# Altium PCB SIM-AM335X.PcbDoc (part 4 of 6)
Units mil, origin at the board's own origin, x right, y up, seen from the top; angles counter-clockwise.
Board outline 4041.51 x 2715.24 mil, 2 copper layers (Top Layer, Bottom Layer); 172 components, 190 nets, 855 pads, 317 vias.
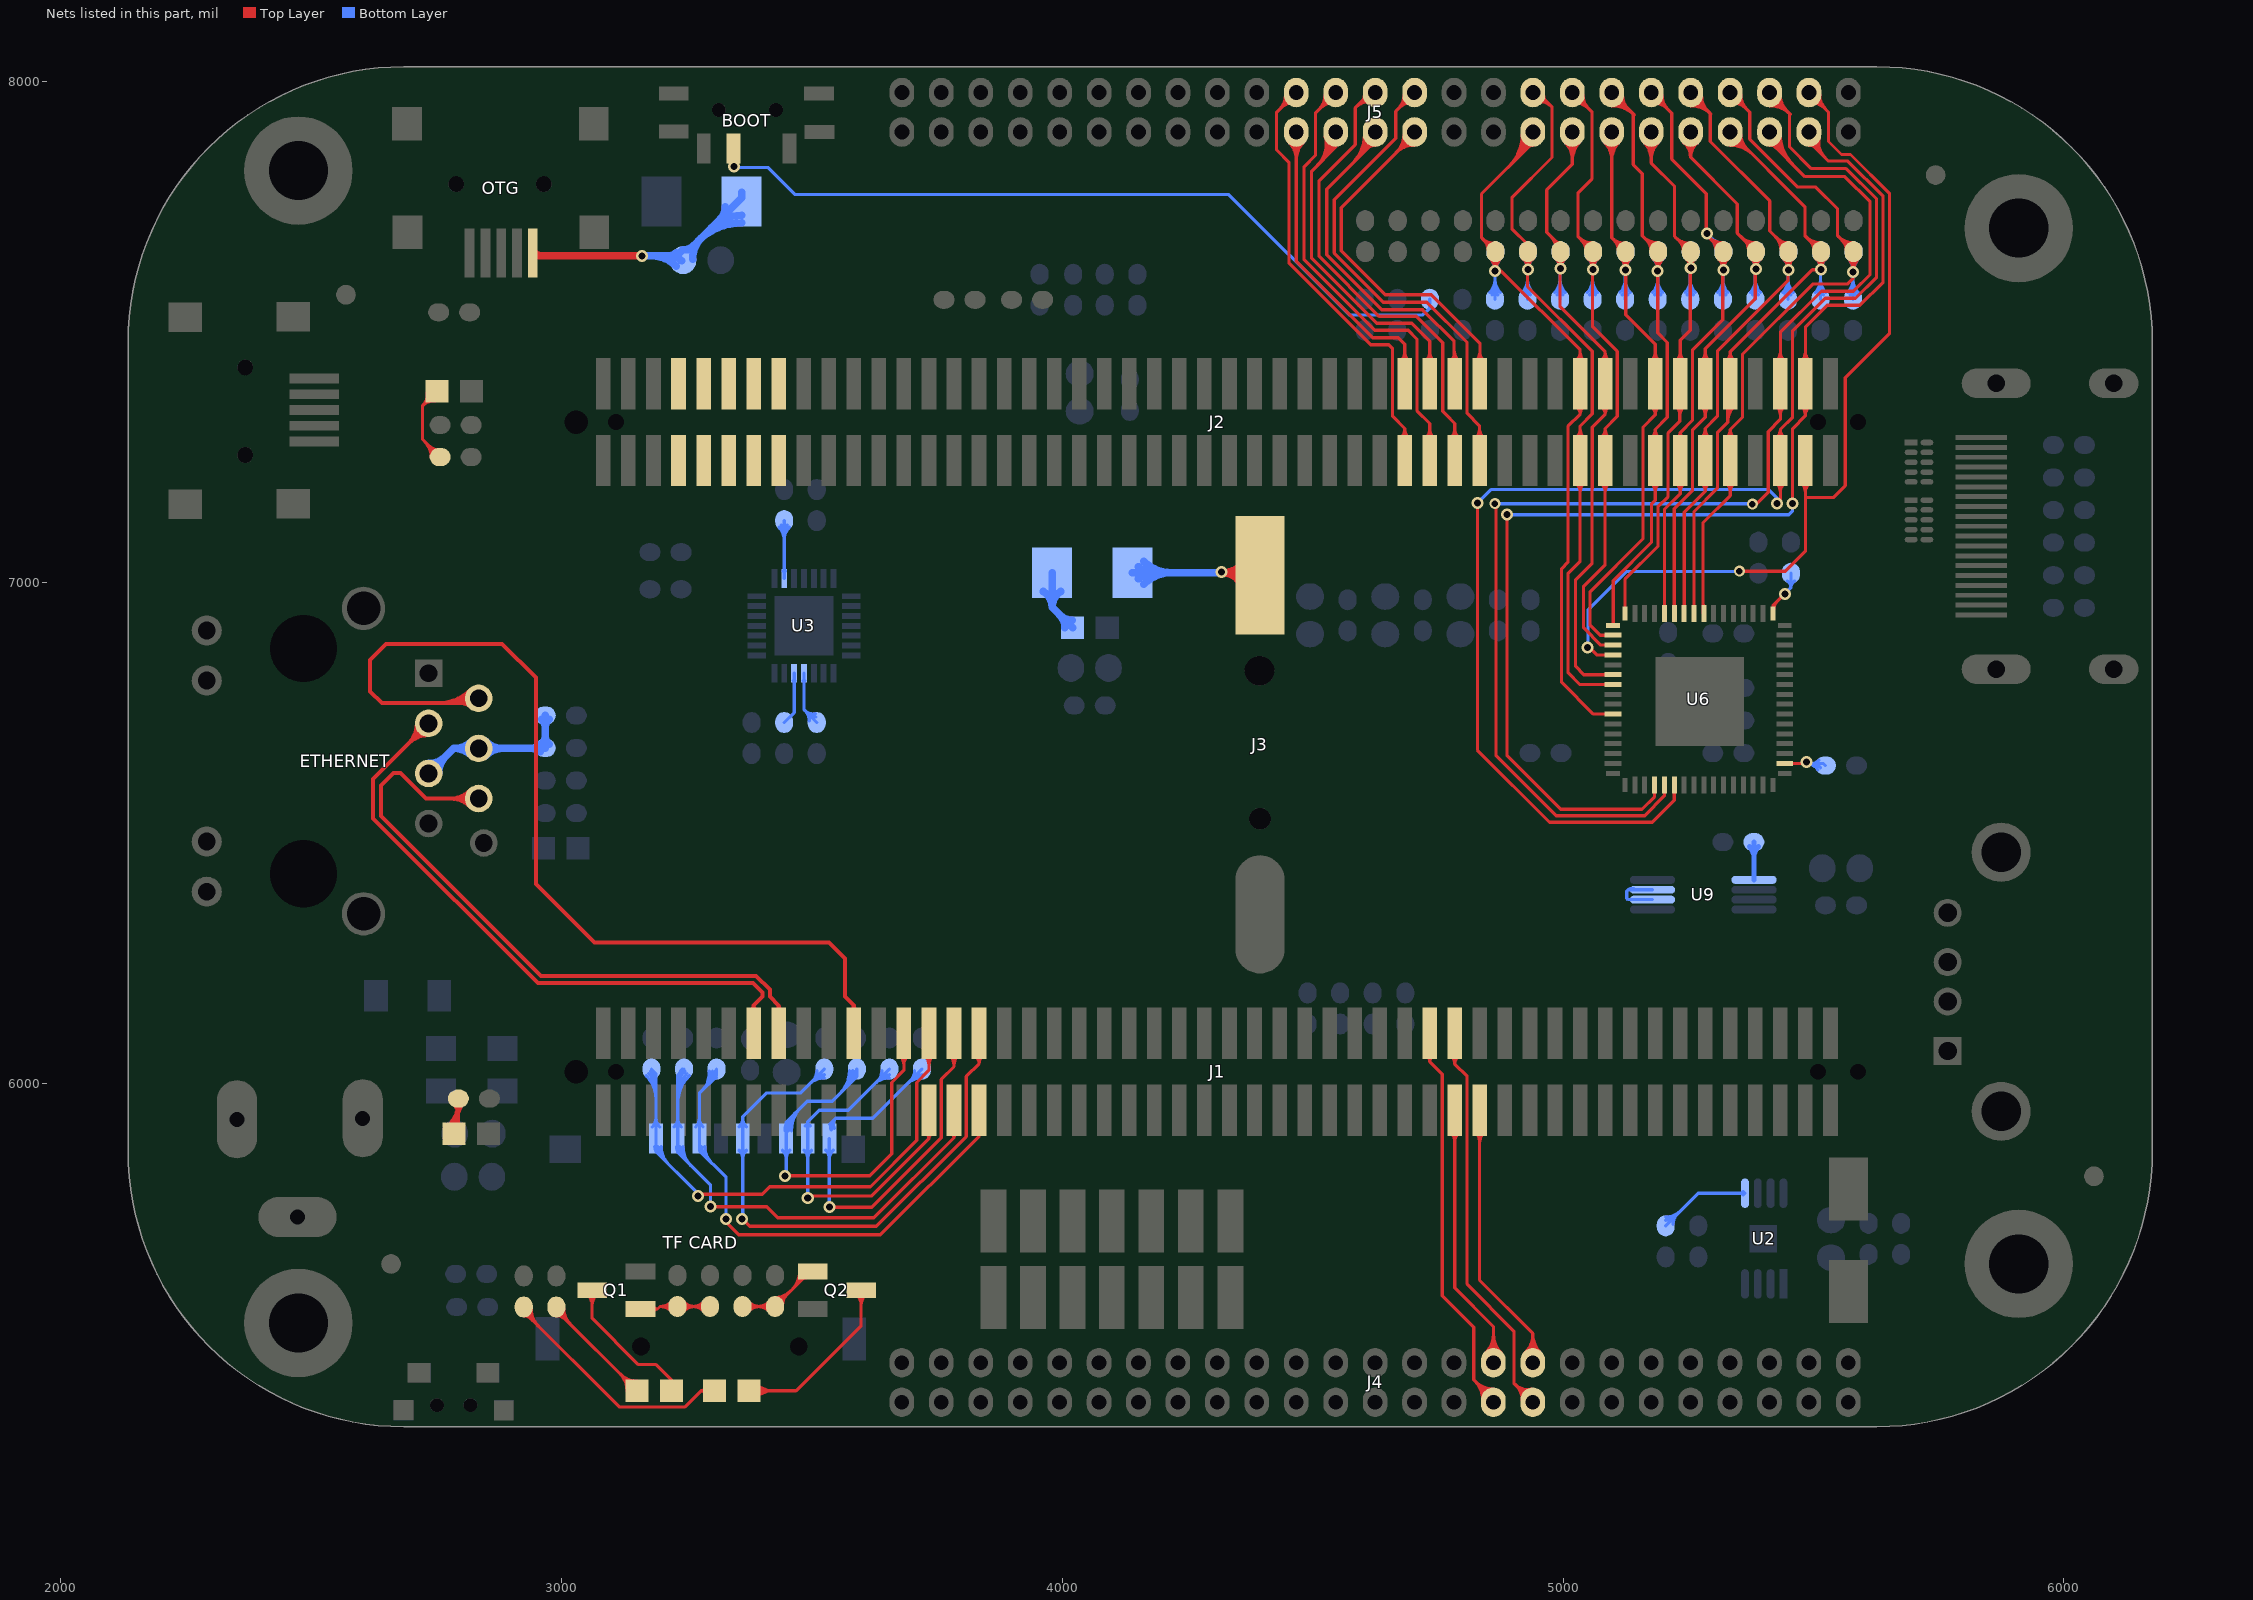
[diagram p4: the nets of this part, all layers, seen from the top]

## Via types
v1: diameter 24, hole 14, Top Layer to Bottom Layer, tented both sides, 206 vias
v2: diameter 22, hole 13, Top Layer to Bottom Layer, tented both sides, 109 vias
v3: diameter 22, hole 14, Top Layer to Bottom Layer, tented both sides, 2 vias

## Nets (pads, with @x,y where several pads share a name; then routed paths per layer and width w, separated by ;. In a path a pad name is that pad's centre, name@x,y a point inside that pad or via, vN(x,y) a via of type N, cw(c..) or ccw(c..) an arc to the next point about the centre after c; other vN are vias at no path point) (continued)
LCD_DATA4: C62.1 J2.80 J5.33 R12.2 R36.1 U6.10 | length 2086.5
  Top Layer w6.5: 4838.75,7687.25 ccw(c4859.96,7708.46) C62.1@4863.34,7678.66 ; 4841.94,7684.06 cw(c4821.88,7664) C62.1@4850.25,7664 ; 4848.29,7677.71 ccw(c4861.9,7691.33) C62.1@4864.07,7672.2 ; C62.1@4854.57,7647.57 cw(c4829.39,7622.39) 4865,7622.39 cw(c4900.61,7622.39) C62.1@4875.43,7647.57 ; C62.1@4859.17,7652.17 cw(c4845.08,7638.08) 4865,7638.08 cw(c4884.92,7638.08) C62.1@4870.83,7652.17 ; v1(4864,7622) v1@4865,7622 ; 4891.91,7830.91 ccw(c4827.73,7895.08) J5.33@4918.49,7895.08 ; 4903,7842 ccw(c4849.93,7895.08) J5.33@4924.99,7895.08 ; 4914.1,7853.1 ccw(c4872.12,7895.08) J5.33@4931.49,7895.08 ; 4925.2,7864.2 ccw(c4894.31,7895.08) J5.33@4937.99,7895.08 ; 4931.1,7870.1 cw(c4939.84,7861.36) J5.33@4939.84,7873.72 ; J5.33@4939.84,7900 4939.84,7878.84 4837.25,7776.25 4837.25,7688.75 C62.1@4865,7661 v1@4865,7622 ; J2.80@5026,7442.16 ccw(c5006.68,7461.48) 5034,7461.48 ccw(c5061.32,7461.48) J2.80@5042,7442.16 ; J2.80@5026.65,7352.32 cw(c5013.06,7336.39) 5034,7336.39 ; J2.80@5041.35,7352.32 ccw(c5054.94,7336.39) 5034,7336.39 ; U6.10@5100,6737.76 5060.62,6737.76 4997,6801.38 4997,7028 5009.68,7040.68 5009.68,7312.07 5034,7336.39 ; v1@4865,7622 4877,7622 5034,7465 J2.80@5034,7397.54 5034,7336.39
  Bottom Layer w6.5: R36.1@4853.57,7579.43 ccw(c4828.39,7604.61) 4864,7604.61 ccw(c4899.61,7604.61) R36.1@4874.43,7579.43 ; R12.2@4854.57,7647.57 cw(c4829.39,7622.39) 4865,7622.39 cw(c4900.61,7622.39) R12.2@4875.43,7647.57 ; R36.1@4858.17,7574.83 ccw(c4844.08,7588.92) 4864,7588.92 ccw(c4883.92,7588.92) R36.1@4869.83,7574.83 ; R12.2@4859.17,7652.17 cw(c4845.08,7638.08) 4865,7638.08 cw(c4884.92,7638.08) R12.2@4870.83,7652.17 ; R36.1@4864,7566 4864,7610 ; v1@4865,7622 R12.2@4865,7661
LCD_DATA5: C63.1 J2.79 J5.34 R11.2 R35.1 U6.7 | length 1880.7
  Top Layer w6.5: C63.1@4920.16,7647.01 cw(c4900.46,7625) v1(4930,7625) ; C63.1@4924.5,7651.85 cw(c4913.48,7639.54) 4930,7639.54 cw(c4946.52,7639.54) C63.1@4935.5,7651.85 ; 4929,7613 4929,7591.4 5058.32,7462.08 5058.32,7337.32 5034,7313 J2.79@5034,7244 5034,7043 5010,7019 5010,6820 5033.16,6796.84 U6.7@5100,6796.84 ; C63.1@4939.84,7647.01 ccw(c4959.54,7625) v1(4930,7625) ; J5.34@4939.84,7978.74 4939.84,7973.63 4954.37,7973.63 4978,7950 4978,7849 4898,7769 4898,7707 4930,7675 C63.1@4930,7661 v1(4930,7625) ; J5.34@4942.08,7965.77 cw(c4949.59,7938.76) 4969.42,7958.58 ; J5.34@4943.82,7959.51 cw(c4953.02,7926.44) 4977.29,7950.71 ; J5.34@4961.2,7973.82 ccw(c4978.15,7973.82) 4966.16,7961.84 ; J2.79@5026,7199.38 cw(c5006.68,7180.06) 5034,7180.06 cw(c5061.32,7180.06) J2.79@5042,7199.38 ; J2.79@5026,7288.62 ccw(c5006.68,7307.94) 5034,7307.94 ccw(c5061.32,7307.94) J2.79@5042,7288.62
  Bottom Layer w6.5: R35.1@4918.57,7579.43 ccw(c4893.39,7604.61) 4929,7604.61 ccw(c4964.61,7604.61) R35.1@4939.43,7579.43 ; R11.2@4920.16,7647.01 cw(c4900.46,7625) v1(4930,7625) ; R35.1@4923.17,7574.83 ccw(c4909.08,7588.92) 4929,7588.92 ccw(c4948.92,7588.92) R35.1@4934.83,7574.83 ; R11.2@4924.5,7651.85 cw(c4913.48,7639.54) 4930,7639.54 cw(c4946.52,7639.54) R11.2@4935.5,7651.85 ; R35.1@4929,7566 4929,7613 ; R11.2@4930,7661 v1(4930,7625) ; R11.2@4939.84,7647.01 ccw(c4959.54,7625) v1(4930,7625)
LCD_DATA6: C64.1 J2.82 J5.35 R10.2 R34.1 U6.6 | length 1769.4
  Top Layer w6.5: 4975.26,7691.74 cw(c4947.52,7664) C64.1@4986.75,7664 ; 4983.48,7683.52 ccw(c4995,7695.05) C64.1@4995,7678.75 ; C64.1@4985.7,7646.55 cw(c4969.8,7627) v1(4995,7627) ; 4986.36,7680.64 cw(c4969.71,7664) C64.1@4993.25,7664 ; 4994,7615 4994,7551 5084,7461 ; J5.35@5003.48,7879.98 cw(c4967.03,7843.52) 5018.58,7843.52 cw(c5070.14,7843.52) J5.35@5033.69,7879.98 ; C64.1@5004.3,7646.55 ccw(c5020.2,7627) v1(4995,7627) ; J5.35@5008.08,7884.57 cw(c4982.72,7859.21) 5018.58,7859.21 cw(c5054.45,7859.21) J5.35@5029.09,7884.57 ; J5.35@5018.58,7900 5018.58,7835.58 4967.25,7784.25 4967.25,7699.75 4995,7672 C64.1@4995,7661 v1(4995,7627) ; J2.82@5076.1,7442.26 ccw(c5057.83,7461) 5084,7461 ; J2.82@5076.55,7352.41 cw(c5062.2,7336) 5084,7336 ; J2.82@5091.45,7352.41 ccw(c5105.8,7336) 5084,7336 ; J2.82@5091.9,7442.26 cw(c5110.17,7461) 5084,7461 ; U6.6@5100,6816.54 5041.46,6816.54 5025,6833 5025,7006 5058,7039 5058,7188.15 5058.32,7188.46 5058.32,7310.32 5084,7336 ; 5084,7336 J2.82@5084,7397.54 5084,7461
  Bottom Layer w6.5: R34.1@4983.57,7579.43 ccw(c4958.39,7604.61) 4994,7604.61 ccw(c5029.61,7604.61) R34.1@5004.43,7579.43 ; R10.2@4985.7,7646.55 cw(c4969.8,7627) v1(4995,7627) ; R34.1@4988.17,7574.83 ccw(c4974.08,7588.92) 4994,7588.92 ccw(c5013.92,7588.92) R34.1@4999.83,7574.83 ; R34.1@4994,7566 4994,7615 ; R10.2@4995,7661 v1(4995,7627) ; R10.2@5004.3,7646.55 ccw(c5020.2,7627) v1(4995,7627)
LCD_DATA7: C65.1 J2.81 J5.36 R9.2 R33.1 U6.3 | length 1809
  Top Layer w6.5: J5.36@5018.58,7978.74 5058,7939.32 5058,7807 5030,7779 5030,7691 C65.1@5060,7661 v1(5060,7625) ; J5.36@5019.03,7965.47 cw(c5020.47,7938.14) 5039.83,7957.5 ; J5.36@5019.37,7958.98 cw(c5021.51,7918.55) 5050.14,7947.18 ; 5031.5,7689.5 ccw(c5057.59,7715.58) C65.1@5059.31,7678.73 ; J5.36@5033.44,7973.82 ccw(c5057.43,7973.82) 5040.47,7956.86 ; 5036.94,7684.06 cw(c5016.88,7664) C65.1@5045.25,7664 ; J5.36@5039.94,7973.82 ccw(c5079.62,7973.82) 5051.56,7945.76 ; 5041.9,7679.1 ccw(c5058.52,7695.71) C65.1@5059.61,7672.24 ; C65.1@5050.16,7647.01 cw(c5030.46,7625) v1(5060,7625) ; C65.1@5054.5,7651.85 cw(c5043.48,7639.54) 5060,7639.54 cw(c5076.52,7639.54) C65.1@5065.5,7651.85 ; 5059,7613 5059,7511.08 5103,7467.08 5108.25,7461.83 5108.25,7458.99 5108.32,7458.92 5108.32,7332.32 5084,7308 J2.81@5084,7244 5084,7036 5041,6993 5041,6910 5075.39,6875.61 U6.3@5100,6875.61 ; C65.1@5069.84,7647.01 ccw(c5089.54,7625) v1(5060,7625) ; J2.81@5076,7199.38 cw(c5056.68,7180.06) 5084,7180.06 cw(c5111.32,7180.06) J2.81@5092,7199.38 ; J2.81@5076,7288.62 ccw(c5056.68,7307.94) 5084,7307.94 ccw(c5111.32,7307.94) J2.81@5092,7288.62
  Bottom Layer w6.5: R33.1@5048.57,7579.43 ccw(c5023.39,7604.61) 5059,7604.61 ccw(c5094.61,7604.61) R33.1@5069.43,7579.43 ; R9.2@5050.16,7647.01 cw(c5030.46,7625) v1(5060,7625) ; R33.1@5053.17,7574.83 ccw(c5039.08,7588.92) 5059,7588.92 ccw(c5078.92,7588.92) R33.1@5064.83,7574.83 ; R9.2@5054.5,7651.85 cw(c5043.48,7639.54) 5060,7639.54 cw(c5076.52,7639.54) R9.2@5065.5,7651.85 ; R33.1@5059,7566 5059,7613 ; R9.2@5060,7661 v1(5060,7625) ; R9.2@5069.84,7647.01 ccw(c5089.54,7625) v1(5060,7625)
LCD_DATA8: C66.1 J2.86 J5.37 R8.2 R32.1 U6.2 | length 1751.2
  Top Layer w6.5: J5.37@5082.22,7879.98 cw(c5045.94,7843.7) 5097.25,7843.7 ; J5.37@5086.82,7884.57 cw(c5061.64,7859.39) 5097.25,7859.39 ; 5097.25,7843.34 cw(c5149.06,7843.34) J5.37@5112.43,7879.98 ; 5097.25,7859.03 cw(c5133.37,7859.03) J5.37@5107.83,7884.57 ; J5.37@5097.32,7900 5097.25,7899.93 5097.25,7688.75 C66.1@5125,7661 v1(5125,7624) ; 5098.75,7687.25 ccw(c5119.96,7708.46) C66.1@5123.34,7678.66 ; U6.2@5100,6895.31 5074.08,6895.31 5054,6915.38 5054,6982 5159.68,7087.68 5159.68,7310.68 5184,7335 ; 5101.94,7684.06 cw(c5081.88,7664) C66.1@5110.25,7664 ; 5108.29,7677.71 ccw(c5121.9,7691.33) C66.1@5124.07,7672.2 ; C66.1@5114.92,7647.23 cw(c5093.19,7624) v1(5125,7624) ; C66.1@5119.36,7651.98 cw(c5107.21,7638.98) 5125,7638.98 cw(c5142.79,7638.98) C66.1@5130.64,7651.98 ; C66.1@5135.08,7647.23 ccw(c5156.81,7624) v1(5125,7624) ; J2.86@5176,7442.16 ccw(c5156.68,7461.48) 5184,7461.48 ccw(c5211.32,7461.48) J2.86@5192,7442.16 ; J2.86@5176.3,7352.63 cw(c5159.96,7335) 5184,7335 ; J2.86@5191.7,7352.63 ccw(c5208.04,7335) 5184,7335 ; v1(5125,7624) 5125,7535 5184,7476 J2.86@5184,7397.54 5184,7335
  Bottom Layer w6.5: R32.1@5113.57,7579.43 ccw(c5088.39,7604.61) 5124,7604.61 ccw(c5159.61,7604.61) R32.1@5134.43,7579.43 ; R8.2@5114.92,7647.23 cw(c5093.19,7624) v1(5125,7624) ; R32.1@5118.17,7574.83 ccw(c5104.08,7588.92) 5124,7588.92 ccw(c5143.92,7588.92) R32.1@5129.83,7574.83 ; R8.2@5119.36,7651.98 cw(c5107.21,7638.98) 5125,7638.98 cw(c5142.79,7638.98) R8.2@5130.64,7651.98 ; R32.1@5124,7566 5124,7612 ; R8.2@5125,7664.5 R8.2@5125,7661 v1(5125,7624) ; R8.2@5135.08,7647.23 ccw(c5156.81,7624) v1(5125,7624)
LCD_DATA9: C67.1 J2.85 J5.38 R7.2 R31.1 U6.1 | length 1798.4
  Top Layer w6.5: J5.38@5097.32,7952.46 cw(c5097.32,7889.02) 5142.18,7933.88 ; J5.38@5097.32,7958.96 cw(c5097.32,7911.22) 5131.09,7944.98 ; J5.38@5097.32,7965.46 cw(c5097.32,7933.41) 5119.99,7956.07 ; J5.38@5097.32,7978.74 5140,7936.06 5140,7835 5158,7817 5158,7693 C67.1@5190,7661 v1@5190,7622 ; U6.1@5100,6915 5100,7004 5176.39,7080.39 5176.39,7157.07 5184,7164.68 J2.85@5184,7244 5184,7306 ; J5.38@5112.18,7973.82 ccw(c5136.17,7973.82) 5119.21,7956.86 ; J5.38@5118.68,7973.82 ccw(c5158.36,7973.82) 5130.3,7945.76 ; 5159.7,7691.3 ccw(c5190,7721.6) C67.1@5190,7678.75 ; 5166.94,7684.06 cw(c5146.88,7664) C67.1@5175.25,7664 ; 5170.8,7680.2 ccw(c5190,7699.41) C67.1@5190,7672.25 ; J2.85@5176,7199.38 cw(c5156.68,7180.06) 5184,7180.06 cw(c5211.32,7180.06) J2.85@5192,7199.38 ; J2.85@5176.44,7289.03 ccw(c5161.19,7306) 5184,7306 ; C67.1@5179.57,7647.57 cw(c5154.39,7622.39) 5190,7622.39 cw(c5225.61,7622.39) C67.1@5200.43,7647.57 ; C67.1@5184.17,7652.17 cw(c5170.08,7638.08) 5190,7638.08 cw(c5209.92,7638.08) C67.1@5195.83,7652.17 ; 5189,7610 5189,7499 5208.32,7479.68 5208.32,7330.32 5184,7306 ; J2.85@5191.56,7289.03 cw(c5206.81,7306) 5184,7306
  Bottom Layer w6.5: J5.38@5097.32,7973.63 J5.38@5097.32,7978.74 ; R31.1@5178.57,7579.43 ccw(c5153.39,7604.61) 5189,7604.61 ccw(c5224.61,7604.61) R31.1@5199.43,7579.43 ; R7.2@5179.57,7647.57 cw(c5156.8,7624.8) v1@5189,7624.8 ; R31.1@5183.17,7574.83 ccw(c5169.08,7588.92) 5189,7588.92 ccw(c5208.92,7588.92) R31.1@5194.83,7574.83 ; R31.1@5189,7566 5189,7610 ; 5189,7636.85 cw(c5209.55,7636.85) R7.2@5195.6,7651.94 ; R7.2@5190,7662 R7.2@5190,7661 5189,7660 v1(5189,7622) cw(c5223.29,7621.99) R7.2@5200.01,7647.17
LCD_DATA10: C68.1 J2.88 J5.39 R6.2 R30.1 U6.64 | length 1522
  Top Layer w6.5: U6.64@5123.62,6938.62 5123.62,7006.62 5189.39,7072.39 5189.39,7151.68 5209.68,7171.98 5209.68,7299.22 5233,7322.54 5233,7396.54 J2.88@5234,7397.54 5234,7484 5254,7504 v1@5254,7628 ; J5.39@5160.96,7879.98 cw(c5124.51,7843.52) 5176.06,7843.52 cw(c5227.62,7843.52) J5.39@5191.17,7879.98 ; J5.39@5165.56,7884.57 cw(c5140.2,7859.21) 5176.06,7859.21 cw(c5211.93,7859.21) J5.39@5186.57,7884.57 ; J5.39@5176.06,7900 5176.06,7837.94 5222.5,7791.5 5222.5,7691.5 5255,7659 v1(5255,7628) ; 5225,7689 ccw(c5250.28,7714.29) C68.1@5253.62,7678.69 ; J2.88@5226,7352.93 cw(c5209.09,7336.02) 5233,7336.02 ; J2.88@5226,7442.16 ccw(c5206.68,7461.48) 5234,7461.48 ccw(c5261.32,7461.48) J2.88@5242,7442.16 ; 5233,7331.19 cw(c5263.74,7331.19) J2.88@5242,7352.93 ; 5233.36,7680.64 cw(c5216.71,7664) C68.1@5240.25,7664 ; 5234.77,7679.23 ccw(c5251.96,7696.41) C68.1@5254.23,7672.21 ; C68.1@5245.99,7646.32 cw(c5231.87,7628) v1(5255,7628) ; C68.1@5264.01,7646.32 ccw(c5278.13,7628) v1(5255,7628)
  Bottom Layer w6.5: R30.1@5243.57,7579.43 ccw(c5218.39,7604.61) 5254,7604.61 ccw(c5289.61,7604.61) R30.1@5264.43,7579.43 ; R30.1@5248.17,7574.83 ccw(c5234.08,7588.92) 5254,7588.92 ccw(c5273.92,7588.92) R30.1@5259.83,7574.83 ; R30.1@5254,7566 5254,7616
LCD_DATA11: C69.1 J2.87 J5.40 R5.2 R29.1 U6.60 | length 1761.3
  Top Layer w6.5: J5.40@5176.06,7978.74 5217,7937.8 5217,7846 5286,7777 5286,7695 C69.1@5320,7661 v1(5320,7624) ; J5.40@5176.27,7965.47 cw(c5177.02,7935.76) 5198.03,7956.77 ; J5.40@5176.44,7958.97 cw(c5177.55,7914.86) 5208.75,7946.06 ; J5.40@5190.92,7973.82 ccw(c5214.91,7973.82) 5197.95,7956.86 ; J5.40@5197.42,7973.82 ccw(c5237.1,7973.82) 5209.04,7945.76 ; U6.60@5202.39,6938.62 5202.39,7146.3 5234,7177.91 J2.87@5234,7244 5234,7299.62 ; J2.87@5226,7199.38 cw(c5206.68,7180.06) 5234,7180.06 cw(c5261.32,7180.06) J2.87@5242,7199.38 ; J2.87@5228.61,7290.56 ccw(c5223.71,7299.62) 5234,7299.62 ; J2.87@5239.39,7290.56 cw(c5244.29,7299.62) 5234,7299.62 ; v1@5289.7,7691.3 ccw(c5320,7721.6) C69.1@5320,7678.75 ; 5296.94,7684.06 cw(c5276.88,7664) C69.1@5305.25,7664 ; 5300.8,7680.2 ccw(c5320,7699.41) C69.1@5320,7672.25 ; C69.1@5309.92,7647.23 cw(c5288.19,7624) v1(5320,7624) ; C69.1@5314.36,7651.98 cw(c5302.21,7638.98) 5320,7638.98 cw(c5337.79,7638.98) C69.1@5325.64,7651.98 ; v1@5319,7624 5319,7525 5258.32,7464.32 5258.32,7323.93 5234,7299.62 ; C69.1@5330.08,7647.23 ccw(c5351.81,7624) v1(5320,7624)
  Bottom Layer w6.5: J5.40@5176.06,7968.91 J5.40@5176.06,7978.74 ; v1(5287,7697) 5320,7664 R5.2@5320,7661 ; R5.2@5305.25,7664 ccw(c5269.64,7664) 5294.82,7689.18 ccw(c5320,7714.36) R5.2@5320,7678.75 ; R29.1@5308.57,7579.43 ccw(c5283.39,7604.61) 5319,7604.61 ccw(c5354.61,7604.61) R29.1@5329.43,7579.43 ; R5.2@5311.75,7664 ccw(c5291.83,7664) 5305.92,7678.08 ccw(c5320,7692.17) R5.2@5320,7672.25 ; R29.1@5313.17,7574.83 ccw(c5299.08,7588.92) 5319,7588.92 ccw(c5338.92,7588.92) R29.1@5324.83,7574.83 ; R29.1@5319,7566 5319,7612
LCD_DATA12: C70.1 J2.90 J5.41 R4.2 R28.1 U6.59 | length 1612.2
  Top Layer w6.5: U6.59@5222.08,6938.62 5222.08,7147.61 5258.32,7183.84 5258.32,7304.32 5284,7330 J2.90@5284,7397.54 5284,7467 5384,7567 5384,7614 ; J5.41@5241.05,7878.74 cw(c5216.2,7849.2) 5254.8,7849.2 ; J5.41@5245.24,7883.71 cw(c5227.95,7863.16) 5254.8,7863.16 cw(c5281.66,7863.16) J5.41@5264.37,7883.71 ; J5.41@5254.8,7900 5254.8,7849.2 ; J5.41@5268.55,7878.74 ccw(c5293.41,7849.2) 5254.8,7849.2 ; J2.90@5276,7352.93 cw(c5256.68,7333.61) 5284,7333.61 cw(c5311.32,7333.61) J2.90@5292,7352.93 ; J2.90@5276,7442.16 ccw(c5256.68,7461.48) 5284,7461.48 ccw(c5311.32,7461.48) J2.90@5292,7442.16 ; 5354.7,7691.3 ccw(c5385,7721.6) C70.1@5385,7678.75 ; 5361.94,7684.06 cw(c5341.88,7664) C70.1@5370.25,7664 ; 5365.8,7680.2 ccw(c5385,7699.41) C70.1@5385,7672.25 ; C70.1@5375.42,7646.78 cw(c5357.67,7626) v1(5385,7626) ; C70.1@5394.58,7646.78 ccw(c5412.33,7626) v1(5385,7626) ; 5254.8,7849.2 5347.75,7756.25 5347.75,7698.25 C70.1@5385,7661 v1(5385,7626)
  Bottom Layer w6.5: R28.1@5373.57,7579.43 ccw(c5348.39,7604.61) 5384,7604.61 ccw(c5419.61,7604.61) R28.1@5394.43,7579.43 ; R4.2@5375.42,7646.78 cw(c5357.67,7626) v1(5385,7626) ; R28.1@5378.17,7574.83 ccw(c5364.08,7588.92) 5384,7588.92 ccw(c5403.92,7588.92) R28.1@5389.83,7574.83 ; R28.1@5384,7566 5384,7614 ; R4.2@5385,7661 v1(5385,7626) ; R4.2@5394.58,7646.78 ccw(c5412.33,7626) v1(5385,7626)
LCD_DATA13: C71.1 J2.89 J5.42 R3.2 R27.1 U6.58 | length 1830.7
  Top Layer w6.5: U6.58@5241.78,6938.62 5241.78,7140.62 5284,7182.85 ; J5.42@5254.8,7978.74 5254.8,7976.2 5294,7937 5294,7881 5412.75,7762.25 5412.75,7702.25 5450,7665 C71.1@5450,7661 v1(5450,7624) ; J5.42@5254.86,7952.46 cw(c5254.99,7895.62) 5295.19,7935.81 ; J5.42@5254.84,7958.96 cw(c5254.94,7917.68) 5284.13,7946.87 ; J5.42@5269.66,7973.82 ccw(c5299.79,7973.82) 5278.48,7952.52 ; J2.89@5276,7288.62 ccw(c5256.68,7307.94) 5284,7307.94 ccw(c5311.32,7307.94) J2.89@5292,7288.62 ; J5.42@5276.16,7973.82 ccw(c5321.98,7973.82) 5289.58,7941.42 ; J2.89@5276.65,7198.78 cw(c5263.06,7182.85) 5284,7182.85 ; J2.89@5291.35,7198.78 ccw(c5304.94,7182.85) 5284,7182.85 ; 5424.11,7690.89 cw(c5397.23,7664) C71.1@5435.25,7664 ; 5426.53,7688.47 ccw(c5450,7711.95) C71.1@5450,7678.75 ; 5435.21,7679.79 cw(c5419.42,7664) C71.1@5441.75,7664 ; 5437.62,7677.38 ccw(c5450,7689.75) C71.1@5450,7672.25 ; C71.1@5439.92,7647.23 cw(c5418.19,7624) v1(5450,7624) ; C71.1@5444.36,7651.98 cw(c5432.21,7638.98) 5450,7638.98 cw(c5467.79,7638.98) C71.1@5455.64,7651.98 ; 5449,7612 5449,7603 5308.32,7462.32 5308.32,7332.32 5284,7308 J2.89@5284,7244 5284,7182.85 ; C71.1@5460.08,7647.23 ccw(c5481.81,7624) v1(5450,7624)
  Bottom Layer w6.5: R27.1@5438.57,7579.43 ccw(c5413.39,7604.61) 5449,7604.61 ccw(c5484.61,7604.61) R27.1@5459.43,7579.43 ; R3.2@5439.92,7647.23 cw(c5418.19,7624) v1(5450,7624) ; R27.1@5443.17,7574.83 ccw(c5429.08,7588.92) 5449,7588.92 ccw(c5468.92,7588.92) R27.1@5454.83,7574.83 ; R3.2@5444.36,7651.98 cw(c5432.21,7638.98) 5450,7638.98 cw(c5467.79,7638.98) R3.2@5455.64,7651.98 ; R27.1@5449,7566 5449,7612 ; R3.2@5450,7661 v1(5450,7624) ; R3.2@5460.08,7647.23 ccw(c5481.81,7624) v1(5450,7624)
LCD_DATA14: C72.1 J2.92 J5.43 R2.2 R26.1 U6.57 | length 1830.6
  Top Layer w6.5: U6.57@5261.47,6938.62 5261.47,7141.93 5308.32,7188.78 5308.32,7299.54 5329,7320.22 5329,7384 5334,7389 J2.92@5334,7397.54 5334,7461 ; J2.92@5326,7352.93 cw(c5318.75,7345.68) 5329,7345.68 ; J2.92@5326.1,7442.26 ccw(c5307.83,7461) 5334,7461 ; 5329,7321.54 cw(c5373.39,7321.54) J2.92@5342,7352.93 ; 5329,7337.23 cw(c5357.7,7337.23) J2.92@5337.41,7357.52 ; J5.43@5333.54,7873.72 cw(c5333.54,7810.28) 5378.4,7855.14 ; J5.43@5333.54,7880.22 cw(c5333.54,7832.48) 5367.31,7866.24 ; J5.43@5333.54,7883.46 J5.43@5333.54,7890.46 ; J5.43@5333.54,7886.72 cw(c5333.54,7854.67) 5356.21,7877.33 ; J5.43@5333.54,7900 5483,7750.54 5483,7693 C72.1@5515,7661 v1(5515,7625) ; J2.92@5341.9,7442.26 cw(c5360.17,7461) 5334,7461 ; J5.43@5348.4,7895.08 ccw(c5372.39,7895.08) 5355.43,7878.12 ; J5.43@5354.9,7895.08 ccw(c5394.58,7895.08) 5366.52,7867.02 ; 5484.7,7691.3 ccw(c5515,7721.6) C72.1@5515,7678.75 ; 5491.94,7684.06 cw(c5471.88,7664) C72.1@5500.25,7664 ; 5495.8,7680.2 ccw(c5515,7699.41) C72.1@5515,7672.25 ; C72.1@5505.16,7647.01 cw(c5485.46,7625) v1(5515,7625) ; C72.1@5509.5,7651.85 cw(c5498.48,7639.54) 5515,7639.54 cw(c5531.52,7639.54) C72.1@5520.5,7651.85 ; C72.1@5524.84,7647.01 ccw(c5544.54,7625) v1(5515,7625) ; 5334,7461 5498,7625 v1(5515,7625)
  Bottom Layer w6.5: R26.1@5503.57,7579.43 ccw(c5478.39,7604.61) 5514,7604.61 ccw(c5549.61,7604.61) R26.1@5524.43,7579.43 ; R2.2@5505.16,7647.01 cw(c5485.46,7625) v1(5515,7625) ; R26.1@5508.17,7574.83 ccw(c5494.08,7588.92) 5514,7588.92 ccw(c5533.92,7588.92) R26.1@5519.83,7574.83 ; R2.2@5509.5,7651.85 cw(c5498.48,7639.54) 5515,7639.54 cw(c5531.52,7639.54) R2.2@5520.5,7651.85 ; R26.1@5514,7566 5514,7613 ; R2.2@5515,7661 v1(5515,7625) ; R2.2@5524.84,7647.01 ccw(c5544.54,7625) v1(5515,7625)
LCD_DATA15: C73.1 J2.91 J5.44 R1.2 R25.1 U6.56 | length 1935.2
  Top Layer w6.5: 5279.25,6959.19 ccw(c5290,6959.19) U6.56@5282.4,6951.59 ; U6.56@5281.16,6938.62 5279.25,6940.53 5279.25,7119.25 5334,7174 J2.91@5334,7244 5334,7306 ; J2.91@5326,7199.38 cw(c5306.68,7180.06) 5334,7180.06 cw(c5361.32,7180.06) J2.91@5342,7199.38 ; J2.91@5326.44,7289.03 ccw(c5311.19,7306) 5334,7306 ; J5.44@5333.54,7978.74 5373,7939.28 5373,7885.78 5468.78,7790 5504.76,7790 5548,7746.76 5548,7693 C73.1@5580,7661 v1@5580,7620 ; J5.44@5333.98,7965.47 cw(c5335.41,7938.08) 5354.81,7957.48 ; J5.44@5334.32,7958.98 cw(c5336.44,7918.45) 5365.13,7947.15 ; J2.91@5341.56,7289.03 cw(c5356.81,7306) 5334,7306 ; J5.44@5348.4,7973.82 ccw(c5372.39,7973.82) 5355.43,7956.86 ; J5.44@5354.9,7973.82 ccw(c5394.58,7973.82) 5366.52,7945.76 ; 5549.7,7691.3 ccw(c5580,7721.6) C73.1@5580,7678.75 ; 5556.94,7684.06 cw(c5536.88,7664) C73.1@5565.25,7664 ; 5560.8,7680.2 ccw(c5580,7699.41) C73.1@5580,7672.25 ; C73.1@5569.57,7647.57 cw(c5544.39,7622.39) 5580,7622.39 cw(c5615.61,7622.39) C73.1@5590.43,7647.57 ; C73.1@5574.17,7652.17 cw(c5560.08,7638.08) 5580,7638.08 cw(c5599.92,7638.08) C73.1@5585.83,7652.17 ; 5579,7608 5567.25,7596.25 5498.25,7596.25 5358.32,7456.32 5358.32,7330.32 5334,7306
  Bottom Layer w6.5: R25.1@5568.57,7579.43 ccw(c5543.39,7604.61) 5579,7604.61 ccw(c5614.61,7604.61) R25.1@5589.43,7579.43 ; R1.2@5569.57,7647.57 cw(c5544.39,7622.39) 5580,7622.39 cw(c5615.61,7622.39) R1.2@5590.43,7647.57 ; R25.1@5573.17,7574.83 ccw(c5559.08,7588.92) 5579,7588.92 ccw(c5598.92,7588.92) R25.1@5584.83,7574.83 ; R1.2@5574.17,7652.17 cw(c5560.08,7638.08) 5580,7638.08 cw(c5599.92,7638.08) R1.2@5585.83,7652.17 ; R25.1@5579,7566 5579,7608 ; v1@5580,7620 R1.2@5580,7661
  other v1: 5579,7620
LCD_DATA16: J2.66 J5.21 | length 802.1
  Top Layer w6.5: J5.21@4452.3,7879.98 cw(c4415.84,7843.52) 4467.4,7843.52 cw(c4518.96,7843.52) J5.21@4482.5,7879.98 ; J5.21@4456.9,7884.57 cw(c4431.54,7859.21) 4467.4,7859.21 cw(c4503.27,7859.21) J5.21@4477.91,7884.57 ; J5.21@4467.4,7900 4467.4,7641.91 4620.31,7489 4671,7489 4684,7476 J2.66@4684,7397.54 ; J2.66@4676,7442.16 ccw(c4656.68,7461.48) 4684,7461.48 ccw(c4711.32,7461.48) J2.66@4692,7442.16
LCD_DATA17: J2.65 J5.22 | length 1028
  Top Layer w6.5: 4434.42,7945.76 ccw(c4406.37,7973.82) J5.22@4446.05,7973.82 ; 4435.85,7947.19 cw(c4464.46,7918.58) J5.22@4466.61,7958.98 ; 4445.52,7956.86 ccw(c4428.56,7973.82) J5.22@4452.55,7973.82 ; 4446.16,7957.5 cw(c4465.5,7938.16) J5.22@4466.96,7965.47 ; J5.22@4467.4,7978.74 4428,7939.34 4428,7864 4453,7839 4453,7637.92 4615.92,7475 4652,7475 4659.68,7467.32 4659.68,7332.32 4684,7308 J2.65@4684,7244 ; J2.65@4676,7288.62 ccw(c4656.68,7307.94) 4684,7307.94 ccw(c4711.32,7307.94) J2.65@4692,7288.62
LCD_DATA18: J2.68 J5.23 | length 934.2
  Top Layer w6.5: 4510.47,7834.47 ccw(c4469.76,7875.18) J5.23@4525.48,7889.7 ; 4518.5,7842.5 ccw(c4482.49,7878.5) J5.23@4531.77,7891.33 ; 4526.52,7850.52 ccw(c4495.23,7881.82) J5.23@4538.06,7892.97 ; 4534.55,7858.55 ccw(c4507.96,7885.13) J5.23@4544.35,7894.61 ; 4542.57,7866.57 ccw(c4520.69,7888.45) J5.23@4550.64,7896.25 ; J5.23@4546.14,7900 4546.14,7870.14 4498,7822 4498,7648.08 4628.08,7518 4698,7518 4734,7482 J2.68@4734,7397.54 ; J2.68@4726,7442.16 ccw(c4706.68,7461.48) 4734,7461.48 ccw(c4761.32,7461.48) J2.68@4742,7442.16
LCD_DATA19: J2.67 J5.24 | length 1055.5
  Top Layer w6.5: 4513.16,7945.76 ccw(c4485.11,7973.82) J5.24@4524.79,7973.82 ; 4514.05,7946.64 cw(c4543.89,7916.8) J5.24@4545.56,7958.97 ; 4524.26,7956.86 ccw(c4507.3,7973.82) J5.24@4531.29,7973.82 ; 4524.55,7957.15 cw(c4544.69,7937.01) J5.24@4545.81,7965.47 ; J5.24@4546.14,7978.74 4506,7938.6 4506,7854 4483,7831 4483,7644.69 4623.69,7504 4691,7504 4708.32,7486.68 4708.32,7343.69 4734,7318.01 J2.67@4734,7244 ; J2.67@4726,7288.62 ccw(c4706.68,7307.94) 4734,7307.94 ccw(c4761.32,7307.94) J2.67@4742,7288.62
LCD_DATA20: J2.70 J5.25 | length 950.8
  Top Layer w6.5: 4579.8,7837.8 ccw(c4522.52,7895.08) J5.25@4603.53,7895.08 ; 4590.9,7848.9 ccw(c4544.71,7895.08) J5.25@4610.03,7895.08 ; 4601.99,7859.99 ccw(c4566.91,7895.08) J5.25@4616.53,7895.08 ; 4609.25,7867.25 cw(c4624.88,7851.61) J5.25@4624.88,7873.72 ; 4613.09,7871.09 ccw(c4589.1,7895.08) J5.25@4623.03,7895.08 ; J5.25@4624.88,7900 4624.88,7882.88 4528,7786 4528,7654.85 4637.85,7545 4720,7545 4720,7544.47 4782.47,7482 4782.47,7399.07 J2.70@4784,7397.54 ; J2.70@4776,7442.16 ccw(c4760.36,7457.8) 4782.47,7457.8 ; 4782.47,7449.47 ccw(c4799.31,7449.47) J2.70@4787.41,7437.56 ; 4782.47,7465.16 ccw(c4815.01,7465.16) J2.70@4792,7442.16
LCD_DATA21: J2.69 J5.26 | length 1068.3
  Top Layer w6.5: 4586.25,7949.25 cw(c4612.98,7922.52) J5.26@4621.53,7959.35 ; 4594.53,7957.53 cw(c4616.1,7935.97) J5.26@4622.99,7965.68 ; 4598.37,7961.37 ccw(c4585.92,7973.82) J5.26@4603.53,7973.82 ; J5.26@4624.88,7978.74 4615.74,7978.74 4585,7948 4585,7874.85 4513,7802.85 4513,7651.46 4632.46,7532 4707,7532 4759.68,7479.32 4759.68,7342.32 4765.39,7336.61 4784,7318.01 J2.69@4784,7244 ; J2.69@4776,7288.62 ccw(c4756.68,7307.94) 4784,7307.94 ccw(c4811.32,7307.94) J2.69@4792,7288.62
LCD_DATA22: J2.72 J5.27 | length 912.3
  Top Layer w6.5: 4666.24,7858.24 cw(c4703.62,7820.85) J5.27@4703.62,7873.72 ; 4667.55,7859.55 ccw(c4632.02,7895.08) J5.27@4682.27,7895.08 ; 4677.33,7869.33 cw(c4703.62,7843.04) J5.27@4703.62,7880.22 ; 4678.64,7870.64 ccw(c4654.21,7895.08) J5.27@4688.77,7895.08 ; J5.27@4703.62,7900 4703.62,7895.62 4557,7749 4557,7662.62 4644.62,7575 4737,7575 4834,7478 J2.72@4834,7397.54 ; J2.72@4826,7442.16 ccw(c4806.68,7461.48) 4834,7461.48 ccw(c4861.32,7461.48) J2.72@4842,7442.16
LCD_DATA23: J2.71 J5.28 | length 1119.2
  Top Layer w6.5: 4670.64,7945.76 ccw(c4642.59,7973.82) J5.28@4682.27,7973.82 ; 4673.39,7948.5 cw(c4699.11,7922.78) J5.28@4702.31,7959.02 ; 4681.74,7956.86 ccw(c4664.78,7973.82) J5.28@4688.77,7973.82 ; 4683.23,7958.35 cw(c4700.71,7940.87) J5.28@4702.89,7965.49 ; J5.28@4703.62,7978.74 4666,7941.12 4666,7887.61 4639.11,7860.72 4638.72,7860.72 4543,7765 4543,7658.23 4641.23,7560 4728,7560 4808.32,7479.68 4808.32,7337.98 4833,7313.3 4833,7245 J2.71@4834,7244 ; J2.71@4826,7288.62 ccw(c4809.09,7305.52) 4833,7305.52 ; 4833,7310.35 ccw(c4863.74,7310.35) J2.71@4842,7288.62
LCD_DE: J2.98 J5.47 U6.20 | length 2586.1
  Top Layer w6.5: v1(4888,7136) 4888,6655.38 4995.38,6548 5157.62,6548 5182.7,6573.08 U6.20@5182.7,6595.99 ; v1(5458.32,7158) 5458.32,7307.32 5484,7333 J2.98@5484,7397.54 5484,7510.23 5527.77,7554 5592.8,7554 5639,7600.2 5639,7771.53 5568.53,7842 5530,7842 5491.02,7880.98 J5.47@5491.02,7895 ; J2.98@5476,7352.93 cw(c5456.68,7333.61) 5484,7333.61 cw(c5511.32,7333.61) J2.98@5492,7352.93 ; J2.98@5476,7442.16 ccw(c5456.68,7461.48) 5484,7461.48 ccw(c5511.32,7461.48) J2.98@5492,7442.16 ; J5.47@5491.02,7873.72 cw(c5491.02,7856.21) 5503.41,7868.59 ; J5.47@5499.12,7893.03 ccw(c5527.4,7885.86) 5506.77,7865.23 ; J5.47@5505.42,7891.43 ccw(c5540.31,7882.58) 5514.86,7857.14 ; J5.47@5511.73,7889.83 ccw(c5553.21,7879.31) 5522.95,7849.05
  Bottom Layer w6.5: v1(4888,7136) 5451,7136 5458.32,7143.32 v1(5458.32,7158)
LCD_HSYNC: J2.95 J5.46 U6.22 | length 2930
  Top Layer w6.5: v1@4829,7158 4829,6666 4973,6522 5178.17,6522 5222.08,6565.92 U6.22@5222.08,6595.99 ; J5.46@5412.32,7965.46 cw(c5412.43,7938.66) 5431.39,7957.61 ; J5.46@5412.28,7978.74 5412.28,7976.72 5452,7937 5452,7871 5496,7827 5565.14,7827 5626,7766.14 5626,7610.08 5583.92,7568 5523.39,7568 5458.32,7502.93 5458.32,7330.32 5434,7306 ; J5.46@5412.35,7958.96 cw(c5412.53,7916.69) 5442.42,7946.58 ; J5.46@5412.38,7952.46 cw(c5412.62,7894.73) 5453.45,7935.55 ; J2.95@5426,7199.38 cw(c5406.68,7180.06) 5434,7180.06 cw(c5461.32,7180.06) J2.95@5442,7199.38 ; J2.95@5426.44,7289.03 ccw(c5411.19,7306) 5434,7306 ; v1(5427,7158) 5434,7165 J2.95@5434,7244 5434,7306 ; J5.46@5427.14,7973.82 ccw(c5456.01,7973.82) 5435.6,7953.4 ; J5.46@5433.64,7973.82 ccw(c5478.2,7973.82) 5446.69,7942.31 ; J2.95@5441.56,7289.03 cw(c5456.81,7306) 5434,7306
  Bottom Layer w6.5: v1@4824,7165 4835,7165 4856,7186 5411,7186 5427,7170 v1(5427,7158)
  other v1: 4829,7159
LCD_PCLK: J2.97 J5.48 U6.4 | length 1930.6
  Top Layer w6.5: v1@5050,6873 5067.08,6855.92 U6.4@5100,6855.92 ; v2(5352,7023) 5444,7023 5484,7063 5484,7170 ; J2.97@5476,7199.38 cw(c5456.68,7180.06) 5484,7180.06 cw(c5511.32,7180.06) J2.97@5492,7199.38 ; J2.97@5484,7244 5484,7170 ; J5.48@5491.02,7978.74 5530,7939.76 5530,7881 5556,7855 5573.91,7855 5652,7776.91 5652,7498 5563.62,7409.62 5563.62,7194 5539.62,7170 5484,7170 ; J5.48@5491.54,7965.48 cw(c5493.17,7938.82) 5512.06,7957.71 ; J5.48@5491.93,7958.99 cw(c5494.35,7919.6) 5522.26,7947.51 ; J5.48@5505.88,7973.82 ccw(c5529.87,7973.82) 5512.91,7956.86 ; J5.48@5512.38,7973.82 ccw(c5552.06,7973.82) 5524,7945.76
  Bottom Layer w6.5: v1@5050,6873 5050,6946 5126.25,7022.25 5351.25,7022.25 v2(5352,7023)
  other v1: 5049,6871
LCD_VSYNC: J2.96 J5.45 U6.21 | length 2736.6
  Top Layer w6.5: v2(4864,7158) 4866.25,7155.75 4866.25,6654.75 4986,6535 5163,6535 5202.39,6574.39 U6.21@5202.39,6595.99 ; v2(5378,7157) 5386,7157 5409.68,7180.68 5409.68,7301.68 5434,7326 J2.96@5434,7397.54 5434,7500 5516,7582 5579.54,7582 5613,7615.46 5613,7760.76 5562.76,7811 5483,7811 5412.28,7881.72 J5.45@5412.28,7900 ; J5.45@5412.28,7873.72 cw(c5412.28,7854.42) 5425.93,7868.07 ; J5.45@5414.14,7895.08 ccw(c5450.88,7895.08) 5424.9,7869.1 ; J5.45@5420.64,7895.08 ccw(c5473.07,7895.08) 5436,7858 ; J2.96@5426,7352.93 cw(c5406.68,7333.61) 5434,7333.61 cw(c5461.32,7333.61) J2.96@5442,7352.93 ; J2.96@5426,7442.16 ccw(c5406.68,7461.48) 5434,7461.48 ccw(c5461.32,7461.48) J2.96@5442,7442.16 ; J5.45@5427.14,7895.08 ccw(c5495.27,7895.08) 5447.09,7846.91 ; J5.45@5433.64,7895.08 ccw(c5517.46,7895.08) 5458.19,7835.81
  Bottom Layer w6.5: v2@4872.01,7157.75 5377.25,7157.75 v2(5378,7157)
MCASP1_ACLKX: J1.69 J4.32 | length 716.4
  Top Layer w6.5: J1.69@4776,5902.38 cw(c4756.68,5883.06) 4784,5883.06 cw(c4811.32,5883.06) J1.69@4792,5902.38 ; J1.69@4784,5947 4784,5592 4860.97,5515.03 J4.32@4860.97,5442.74 ; J4.32@4845.87,5462.76 ccw(c4809.41,5499.22) 4860.97,5499.22 ccw(c4912.53,5499.22) J4.32@4876.07,5462.76 ; J4.32@4850.47,5458.17 ccw(c4825.1,5483.53) 4860.97,5483.53 ccw(c4896.84,5483.53) J4.32@4871.47,5458.17
MCASP1_AXR0: J1.71 J4.34 | length 728.9
  Top Layer w6.5: J1.71@4826,5902.38 cw(c4808.49,5884.88) 4833.25,5884.88 ; 4833.25,5881.25 cw(c4863.13,5881.25) J1.71@4842,5902.38 ; J1.71@4834,5947 4833.25,5946.25 4833.25,5607.75 4939.71,5501.29 J4.34@4939.71,5442.74 ; J4.34@4924.61,5462.76 ccw(c4888.15,5499.22) 4939.71,5499.22 ccw(c4991.27,5499.22) J4.34@4954.81,5462.76 ; J4.34@4929.21,5458.17 ccw(c4903.84,5483.53) 4939.71,5483.53 ccw(c4975.58,5483.53) J4.34@4950.21,5458.17
MCASP1_AXR1: J1.68 J4.31 | length 951
  Top Layer w6.5: J1.68@4728.2,6054.21 cw(c4722.11,6044) 4734,6044 ; J1.68@4734,6100.54 4734,6044 ; J1.68@4739.8,6054.21 ccw(c4745.89,6044) 4734,6044 ; 4824.44,5405.56 cw(c4787.79,5368.92) J4.31@4839.61,5368.92 ; 4824.7,5405.3 ccw(c4860.97,5441.57) J4.31@4860.97,5390.28 ; 4835.53,5394.47 cw(c4809.98,5368.92) J4.31@4846.11,5368.92 ; 4835.79,5394.21 ccw(c4860.97,5419.38) J4.31@4860.97,5383.78 ; J4.31@4860.97,5364 4860.97,5369.03 4821.61,5408.39 4821.61,5513.39 4759,5576 4759,6019 4734,6044
MCASP1_FSX: J1.70 J4.33 | length 947.8
  Top Layer w6.5: J1.70@4776.55,6055.41 cw(c4762.2,6039) 4784,6039 ; J1.70@4784,6100.54 4784,6039 ; J1.70@4791.45,6055.41 ccw(c4805.8,6039) 4784,6039 ; 4904.46,5399.25 ccw(c4928.75,5423.53) J4.33@4935.51,5389.86 ; 4906.73,5396.98 cw(c4878.68,5368.92) J4.33@4918.35,5368.92 ; 4913.04,5390.67 ccw(c4931.62,5409.24) J4.33@4936.79,5383.49 ; 4917.83,5385.88 cw(c4900.87,5368.92) J4.33@4924.85,5368.92 ; J4.33@4939.71,5364 4902,5401.71 4902,5506 4808.32,5599.68 4808.32,6014.68 4784,6039
MMC0_CD: "TF CARD.9" J1.30 R71.2 | length 1068.7
  Top Layer w6.5: v1@3536,5760 3543,5753 3619.54,5753 3758.32,5891.78 3758.32,5901 3758.32,6008.32 3784,6034 J1.30@3784,6100.54 ; J1.30@3776,6055.93 cw(c3756.68,6036.61) 3784,6036.61 cw(c3811.32,6036.61) J1.30@3792,6055.93
  Bottom Layer w6.5: 3528.03,5867.16 cw(c3511.19,5850.32) 3535,5850.32 ; v1(3535,5754) 3535,5889.88 3535.47,5890.35 ; 3535,5848.05 cw(c3562.03,5848.05) 3542.92,5867.16 ; 3535.47,5918.47 3547.88,5930.88 ; 3539.05,5907.96 cw(c3551.69,5914.54) 3541.61,5924.61 ; 3544.81,5910.96 cw(c3559.93,5918.83) 3547.88,5930.88 ; 3689.7,5998.7 cw(c3720,5968.4) R71.2@3720,6011.25 ; 3696.94,6005.94 ccw(c3676.88,6026) R71.2@3705.25,6026 ; 3700.8,6009.8 cw(c3720,5990.59) R71.2@3720,6017.75 ; R71.2@3720,6029 3621.88,5930.88 3547.88,5930.88
MMC0_CLKO: "TF CARD.5" J1.32 R68.2 | length 1342.9
  Top Layer w6.5: v1(3361,5730) 3376,5715 3629,5715 3808.32,5894.32 3808.32,6014.32 3834,6040 ; J1.32@3826.82,6055.18 cw(c3814.36,6040) 3834,6040 ; J1.32@3834,6100.54 3834,6040 ; J1.32@3841.18,6055.18 ccw(c3853.64,6040) 3834,6040
  Bottom Layer w6.5: 3354.8,5867.16 cw(c3336.82,5849.19) 3362.24,5849.19 cw(c3387.66,5849.19) 3369.69,5867.16 ; 3354.8,5913.55 ccw(c3336.82,5931.52) 3362.24,5931.52 ccw(c3387.66,5931.52) 3369.69,5913.55 ; v1@3362,5730 3362,5826 3362.24,5826.24 3362.24,5890.35 3362.24,5934.24 3409,5981 3477,5981 R68.2@3525,6029 ; 3494.7,5998.7 cw(c3525,5968.4) R68.2@3525,6011.25 ; 3501.94,6005.94 ccw(c3481.88,6026) R68.2@3510.25,6026 ; 3505.8,6009.8 cw(c3525,5990.59) R68.2@3525,6017.75
MMC0_CMD: "TF CARD.3" J1.31 R67.2 | length 1211.7
  Top Layer w6.5: v1@3322,5730 3354,5698 3637,5698 3834,5895 ; J1.31@3830.63,5899.58 cw(c3829.2,5895) 3834,5895 ; J1.31@3834,5947 3834,5895 ; J1.31@3837.37,5899.58 ccw(c3838.8,5895) 3834,5895
  Bottom Layer w6.5: 3268.18,5913.55 ccw(c3250.21,5931.52) 3275.63,5931.52 ccw(c3301.05,5931.52) 3283.08,5913.55 ; 3279.66,5874.61 ccw(c3309.27,5874.61) 3288.33,5853.67 ; 3281.13,5986.13 ccw(c3246.52,6020.74) R67.2@3295.3,6024.78 ; 3286.16,5874.61 ccw(c3331.46,5874.61) 3299.43,5842.57 ; 3291.05,5996.05 ccw(c3264.84,6022.26) R67.2@3301.78,6025.32 ; 3300.96,6005.96 ccw(c3283.15,6023.78) R67.2@3308.26,6025.86 ; 3303.6,6008.6 cw(c3310,6002.2) R67.2@3310,6011.25 ; R67.2@3310,6029 3310,6015 3275.63,5980.63 3275.63,5890.35 3275.63,5866.37 3329,5813 3329,5737 v1@3322,5730
  other v1: 3329,5730
MMC0_DAT0: "TF CARD.7" J1.26 R69.2 | length 1098.9
  Top Layer w6.5: v1(3447,5816) 3616,5816 3659.68,5859.68 3659.68,5891.78 3659.68,6002.22 3684,6026.54 J1.26@3684,6100.54 ; J1.26@3676,6055.93 cw(c3656.68,6036.61) 3684,6036.61 cw(c3711.32,6036.61) J1.26@3692,6055.93
  Bottom Layer w6.5: 3441.41,5867.16 cw(c3423.44,5849.19) 3448.86,5849.19 cw(c3474.28,5849.19) 3456.3,5867.16 ; 3446.39,5906.1 cw(c3480.88,5906.1) 3456.49,5930.49 ; v1@3448.86,5815.86 3448.86,5890.35 3448.86,5922.86 3491,5965 3541,5965 3590,6014 R69.2@3590,6029 ; 3452.89,5906.1 cw(c3503.07,5906.1) 3467.59,5941.59 ; 3459.39,5906.1 cw(c3525.26,5906.1) 3478.68,5952.68 ; 3556.33,5980.33 ccw(c3510.67,6026) R69.2@3575.25,6026 ; 3567.43,5991.43 ccw(c3532.86,6026) R69.2@3581.75,6026 ; 3578.53,6002.53 ccw(c3555.05,6026) R69.2@3588.25,6026
MMC0_DAT1: "TF CARD.8" J1.27 R70.2 | length 871.5
  Top Layer w6.5: v1(3492,5772) 3492,5773 3494.75,5775.75 3619.75,5775.75 3734,5890 ; J1.27@3728.02,5900.78 cw(c3721.3,5890) 3734,5890 ; J1.27@3734,5947 3734,5890 ; J1.27@3739.98,5900.78 ccw(c3746.7,5890) 3734,5890
  Bottom Layer w6.5: 3484.72,5867.16 cw(c3466.75,5849.19) 3492.17,5849.19 cw(c3517.59,5849.19) 3499.61,5867.16 ; 3486.98,5915.26 ccw(c3481.94,5924.17) 3492.17,5924.17 ; v1(3492,5772) 3492,5823 3492.17,5823.17 3492.17,5890.35 3492.17,5924.17 ; 3497.35,5915.26 cw(c3502.39,5924.17) 3492.17,5924.17 ; 3624.7,5998.7 cw(c3655,5968.4) R70.2@3655,6011.25 ; 3631.94,6005.94 ccw(c3611.88,6026) R70.2@3640.25,6026 ; 3635.8,6009.8 cw(c3655,5990.59) R70.2@3655,6017.75 ; R70.2@3655,6029 3573,5947 3515,5947 3492.17,5924.17
MMC0_DAT2: "TF CARD.1" J1.28 R55.2 | length 1282.3
  Top Layer w6.5: v1@3271,5779 3401,5779 3416.25,5794.25 3617.25,5794.25 3709.68,5886.68 3709.68,6002.22 3734,6026.54 J1.28@3734,6100.54 ; J1.28@3726,6055.93 cw(c3706.68,6036.61) 3734,6036.61 cw(c3761.32,6036.61) J1.28@3742,6055.93
  Bottom Layer w6.5: R55.2@3169.57,6015.57 cw(c3122.62,5968.62) 3189.02,5968.62 ; R55.2@3174.17,6020.17 cw(c3138.32,5984.32) 3189.02,5984.32 ; R55.2@3178.76,6024.76 cw(c3154.01,6000.01) 3189.02,6000.01 ; R55.2@3180,6029 3189.02,6019.98 3189.02,5890.35 3189.02,5863.98 3268,5785 v1@3268,5776 ; 3181.57,5913.55 ccw(c3163.6,5931.52) 3189.02,5931.52 ccw(c3214.44,5931.52) 3196.46,5913.55 ; 3186.55,5874.61 ccw(c3206.22,5874.61) 3192.31,5860.69 ; 3193.05,5874.61 ccw(c3228.42,5874.61) 3203.41,5849.59 ; 3199.55,5874.61 ccw(c3250.61,5874.61) 3214.5,5838.5
  other v1: 3273,5776
MMC0_DAT3: "TF CARD.2" J1.29 R56.2 | length 1247.9
  Top Layer w6.5: v1@3298,5754 3410,5754 3432,5732 3624,5732 3784,5892 ; J1.29@3778.9,5900.28 cw(c3774.72,5892) 3784,5892 ; J1.29@3784,5947 3784,5892 ; J1.29@3789.1,5900.28 ccw(c3793.28,5892) 3784,5892
  Bottom Layer w6.5: 3224.88,5913.55 ccw(c3206.9,5931.52) 3232.32,5931.52 ccw(c3257.74,5931.52) 3239.77,5913.55 ; 3229.85,5874.61 ccw(c3252.68,5874.61) 3236.54,5858.46 ; 3232.32,5959.78 cw(c3311.22,5959.78) R56.2@3255.43,6015.57 ; 3232.32,5975.48 cw(c3295.52,5975.48) R56.2@3250.83,6020.17 ; 3232.32,5991.17 cw(c3279.83,5991.17) R56.2@3246.24,6024.76 ; 3232.32,6006.86 cw(c3264.14,6006.86) R56.2@3241.64,6029.36 ; 3236.35,5874.61 ccw(c3274.88,5874.61) 3247.64,5847.36 ; 3242.85,5874.61 ccw(c3297.07,5874.61) 3258.73,5836.27 ; R56.2@3245,6029 3232.32,6016.32 3232.32,5890.35 3232.32,5862.68 3298,5797 v1(3298,5755)
MMC1_CLK: J2.15
MMC1_CMD: J2.16
MMC1_DAT0: J2.8
MMC1_DAT1: J2.7
MMC1_DAT2: J2.10
MMC1_DAT3: J2.9
MMC1_DAT4: J2.12
MMC1_DAT5: J2.11
MMC1_DAT6: J2.14
MMC1_DAT7: J2.13
NetBOOT_2: BOOT.2 R38.1 | length 1536.9
  Bottom Layer w6.5: v1@3344,7829 v1@3344,7831 ; v1(3345,7831) 3347,7829 3413,7829 3467,7775 4333,7775 4573.25,7534.75 4720.28,7534.75 4734,7548.47 R38.1@4734,7566
NetC29_1: C29.1 ETHERNET.4 ETHERNET.5 R50.2 | length 666
  Bottom Layer w15: ETHERNET.5@2735,6619.2 2785,6669.2 ETHERNET.4@2835,6669.2 2967.2,6669.2 C29.1@2968,6670 R50.2@2968,6735 ; ETHERNET.5@2735,6639.2 ccw(c2735,6687.48) 2769.14,6653.34 ccw(c2803.28,6619.2) ETHERNET.5@2755,6619.2 ; ETHERNET.4@2820.86,6655.06 ccw(c2786.72,6620.92) 2786.72,6669.2 ccw(c2786.72,6717.48) ETHERNET.4@2820.86,6683.34 ; ETHERNET.4@2849.14,6655.06 cw(c2883.28,6620.92) 2883.28,6669.2 cw(c2883.28,6717.48) ETHERNET.4@2849.14,6683.34 ; 2937.72,6669.2 ccw(c2937.72,6697.28) C29.1@2957.58,6677.42 ; 2941.58,6669.2 cw(c2941.58,6646.58) C29.1@2957.58,6662.58 ; C29.1@2960.58,6677.42 ccw(c2942.65,6695.35) 2968,6695.35 ccw(c2993.35,6695.35) C29.1@2975.42,6677.42 ; R50.2@2960.58,6727.58 cw(c2942.65,6709.65) 2968,6709.65 cw(c2993.35,6709.65) R50.2@2975.42,6727.58
NetD1_1: D1.1 J3.1 | length 575.2
  Top Layer w15: 4344.09,7020 cw(c4344.09,6989.98) J3.1@4371.02,7003.22 ; J3.1@4357.56,6996.61 ccw(c4320,6978.15) v1@4320,7020 ; J3.1@4362.06,7040.59 cw(c4320,7073.24) v1@4320,7020 ; J3.1@4395,7015 4390,7020 v1@4320,7020
  Bottom Layer w15: D1.1@4140,7020 v1@4320,7020 ; D1.1@4152.37,7007.63 cw(c4182.25,6977.75) 4182.25,7020 cw(c4182.25,7062.25) D1.1@4152.37,7032.37 ; D1.1@4162.98,6997.02 cw(c4218.46,6941.54) 4218.46,7020 cw(c4218.46,7098.46) D1.1@4162.98,7042.98
  other v1: 4318,7021
NetD1_2: D1.2 R44.2 | length 259
  Bottom Layer w15: D1.2@3962.63,6982.53 cw(c3942.7,6951) 3980,6951 ; D1.2@3980,7020 3980,6951 ; 3994.54,6936.46 cw(c3968.08,6910) R44.2@4005.5,6910 ; 3995.75,6935.25 ccw(c4020.5,6960.01) R44.2@4020.5,6925 ; D1.2@3997.37,6982.53 ccw(c4017.3,6951) 3980,6951 ; R44.2@4021,6910 3980,6951
NetD2_1: D2.1 FB2.2 OTG.1 | length 861.9
  Top Layer w15: OTG.1@2942.99,7658.32 2948.77,7652.54 v1(3161.46,7652.54) v1@3163,7651 ; OTG.1@2944.65,7659.97 ccw(c2962.6,7677.93) 2962.6,7652.54
  Bottom Layer w15: v1(3161.46,7652.54) 3230.04,7652.54 3242.5,7665 3256,7665 3360,7769 D2.1@3360,7780 ; 3180.14,7652.54 cw(c3180.14,7582.64) FB2.2@3229.56,7632.06 ; 3214.12,7652.54 ccw(c3214.12,7674.38) FB2.2@3229.56,7658.94 ; 3216.36,7652.54 cw(c3216.36,7618.86) FB2.2@3240.17,7642.67 ; FB2.2@3243,7664.5 ccw(c3243,7694.68) 3264.34,7673.34 ; FB2.2@3262,7645.5 cw(c3323.56,7645.5) 3280.03,7689.03 ; 3273.79,7682.79 cw(c3360,7596.58) D2.1@3360,7718.5 ; 3299.4,7708.4 cw(c3360,7647.8) D2.1@3360,7733.5 ; 3317.25,7726.25 ccw(c3292.49,7751) D2.1@3327.5,7751
NetLED1_1: LED1.1 R17.1 | length 432.9
  Top Layer w6.5: R17.1@2990,5536.25 cw(c2990,5508.29) 3009.77,5528.06 ; R17.1@2990,5554 2990,5547.83 LED1.1@3151.1,5386.73 ; R17.1@2998.25,5551 ccw(c3025.82,5551) 3006.33,5531.5 ; R17.1@3004.75,5551 ccw(c3048.01,5551) 3017.42,5520.41 ; 3117.38,5420.45 cw(c3083.67,5386.73) LED1.1@3131.35,5386.73 ; 3118.59,5419.24 ccw(c3150.6,5451.25) LED1.1@3150.6,5405.98 ; 3128.48,5409.35 cw(c3105.86,5386.73) LED1.1@3137.85,5386.73 ; LED1.1@3129.69,5408.14 ccw(c3150.6,5429.06) LED1.1@3150.6,5399.48
NetLED1_2: LED1.2 Q1.3 | length 334.3
  Top Layer w6.5: Q1.3@3052.61,5578.56 cw(c3031.28,5557.23) 3061.45,5557.23 cw(c3091.62,5557.23) Q1.3@3070.29,5578.56 ; Q1.3@3061.45,5587.4 3061.45,5531.55 3154,5439 3189.1,5439 3220.1,5408 LED1.2@3220.1,5386.73
NetLED2_1: LED2.1 R20.1 | length 586.2
  Top Layer w6.5: R20.1@2925,5536.25 cw(c2925,5515.13) 2939.94,5530.06 ; R20.1@2925,5554 2925,5545 3115.52,5354.48 3247.14,5354.48 3279.39,5386.73 ; R20.1@2933.25,5551 ccw(c2967.65,5551) 2943.33,5526.67 ; R20.1@2939.75,5551 ccw(c2989.84,5551) 2954.42,5515.58 ; LED2.1@3287.23,5380.97 ccw(c3279.39,5378.51) 3279.39,5386.73 ; LED2.1@3287.23,5392.49 cw(c3279.39,5394.95) 3279.39,5386.73 ; LED2.1@3306.1,5386.73 3279.39,5386.73
NetLED2_2: LED2.2 Q2.3 | length 517
  Top Layer w6.5: LED2.2@3375.1,5386.73 3468.73,5386.73 3598.55,5516.55 Q2.3@3598.55,5587.6 ; LED2.2@3384.61,5377.72 cw(c3406.38,5355.95) 3406.38,5386.73 cw(c3406.38,5417.51) LED2.2@3384.61,5395.75 ; LED2.2@3389.21,5373.12 cw(c3422.07,5340.26) 3422.07,5386.73 cw(c3422.07,5433.21) LED2.2@3389.21,5400.34 ; Q2.3@3589.71,5578.76 cw(c3568.38,5557.43) 3598.55,5557.43 cw(c3628.72,5557.43) Q2.3@3607.39,5578.76
NetLED3_1: LED3.1 R21.2 | length 341.1
  Top Layer w6.5: 2727.7,7281.3 cw(c2697.4,7251) R21.2@2740.25,7251 ; LED3.1@2731.93,7379.63 cw(c2701.63,7375.56) 2723.25,7353.94 cw(c2745.68,7331.51) LED3.1@2749,7363.05 ; LED3.1@2732.54,7363.22 ccw(c2718.01,7377.76) LED3.1@2738.38,7380.5 ; LED3.1@2732.89,7363.57 cw(c2747.51,7348.94) LED3.1@2749.68,7369.52 ; 2734.94,7274.06 ccw(c2755,7294.12) R21.2@2755,7265.75 ; 2738.8,7270.2 cw(c2719.59,7251) R21.2@2746.75,7251 ; R21.2@2758,7251 2723,7286 2723,7353.69 LED3.1@2751.51,7382.2 LED3.1@2760.51,7373.2
NetLED4_1: LED4.1 R42.2 | length 315.6
  Top Layer w6.5: LED4.1@2772.38,5913.61 ccw(c2718.99,5966.99) R42.2@2794.49,5966.99 ; LED4.1@2776.97,5909.02 ccw(c2734.69,5951.3) 2794.49,5951.3 ; LED4.1@2781.57,5904.42 ccw(c2750.38,5935.61) 2794.49,5935.61 ; R42.2@2784.06,5959.57 cw(c2758.88,5934.39) 2794.49,5934.39 cw(c2830.1,5934.39) R42.2@2804.92,5959.57 ; LED4.1@2785.49,5900 2794.49,5909 R42.2@2794.49,5970 ; R42.2@2788.65,5964.17 cw(c2774.57,5950.08) 2794.49,5950.08 cw(c2814.41,5950.08) R42.2@2800.32,5964.17 ; 2794.49,5925.95 ccw(c2811.94,5925.95) LED4.1@2799.6,5913.61
NetQ1_1: Q1.1 R18.2 R23.2 | length 421.9
  Top Layer w6.5: Q1.1@3158,5550 3192,5550 ; Q1.1@3182.96,5544.41 cw(c3192,5539.89) 3192,5550 ; Q1.1@3182.96,5555.59 ccw(c3192,5560.11) 3192,5550 ; R23.2@3221.2,5544.74 ccw(c3197,5521.32) 3197,5555 ; R23.2@3221.2,5565.26 cw(c3197,5588.68) 3197,5555 ; R23.2@3225.88,5549.26 ccw(c3212.34,5536.16) 3212.34,5555 ccw(c3212.34,5573.84) R23.2@3225.88,5560.74 ; R23.2@3237.64,5549.17 cw(c3251.72,5535.08) 3251.72,5555 cw(c3251.72,5574.92) R23.2@3237.64,5560.83 ; R23.2@3242.23,5544.57 cw(c3267.41,5519.39) 3267.41,5555 cw(c3267.41,5590.61) R23.2@3242.23,5565.43 ; R18.2@3286.37,5544.57 ccw(c3261.19,5519.39) 3261.19,5555 ccw(c3261.19,5590.61) R18.2@3286.37,5565.43 ; R18.2@3290.97,5549.17 ccw(c3276.89,5535.08) 3276.89,5555 ccw(c3276.89,5574.92) R18.2@3290.97,5560.83 ; R18.2@3296.8,5555 R23.2@3231.8,5555 3197,5555 ; 3192,5550 3197,5555
NetQ2_1: Q2.1 R22.2 R24.2 | length 495.9
  Top Layer w6.5: R22.2@3361.8,5555 R24.2@3426.8,5555 3496.8,5625 Q2.1@3502,5625 ; R22.2@3367.64,5549.17 cw(c3381.72,5535.08) 3381.72,5555 cw(c3381.72,5574.92) R22.2@3367.64,5560.83 ; R22.2@3372.23,5544.57 cw(c3397.41,5519.39) 3397.41,5555 cw(c3397.41,5590.61) R22.2@3372.23,5565.43 ; R24.2@3416.37,5544.57 ccw(c3391.19,5519.39) 3391.19,5555 ccw(c3391.19,5590.61) R24.2@3416.37,5565.43 ; R24.2@3420.97,5549.17 ccw(c3406.89,5535.08) 3406.89,5555 ccw(c3406.89,5574.92) R24.2@3420.97,5560.83 ; R24.2@3426.8,5566.25 ccw(c3426.8,5593.41) 3446.01,5574.2 ; R24.2@3426.8,5572.75 ccw(c3426.8,5615.6) 3457.11,5585.3 ; R24.2@3441.55,5558 cw(c3469.92,5558) 3449.86,5578.06 ; 3460.82,5589.01 ccw(c3424.83,5625) Q2.1@3475.72,5625 ; 3471.91,5600.11 ccw(c3447.02,5625) Q2.1@3482.22,5625 ; Q2.1@3481.54,5609.73 cw(c3488.22,5603.05) Q2.1@3488.22,5612.5
NetR51_2: R51.2 U3.9 | length 212.8
  Bottom Layer w6.5: R51.2@3434.57,7110.57 cw(c3409.39,7085.39) 3445,7085.39 cw(c3480.61,7085.39) R51.2@3455.43,7110.57 ; R51.2@3439.17,7115.17 cw(c3425.08,7101.08) 3445,7101.08 cw(c3464.92,7101.08) R51.2@3450.83,7115.17 ; U3.9@3443.24,7023.22 ccw(c3438.99,7027.46) 3445,7027.46 ; 3445,7028.03 ccw(c3451.81,7028.03) U3.9@3447,7023.22 ; R51.2@3445,7124 3445,7008.66 U3.9@3445.12,7008.54
NetR52_1: R52.1 U3.25 | length 179.6
  Bottom Layer w6.5: U3.25@3482.61,6804.89 cw(c3478.08,6800.36) 3484.49,6800.36 cw(c3490.9,6800.36) U3.25@3486.37,6804.89 ; U3.25@3484.49,6819.57 3484.49,6746.51 R52.1@3510,6721 ; 3485.99,6745.01 ccw(c3502.76,6761.78) R52.1@3507.23,6738.49 ; 3486.94,6744.06 cw(c3466.88,6724) R52.1@3495.25,6724 ; 3494.66,6736.34 ccw(c3505.55,6747.23) R52.1@3508.45,6732.1
NetR53_1: R53.1 U3.26 | length 116.8
  Bottom Layer w6.5: R53.1@3445,6721 3464.8,6740.8 U3.26@3464.8,6819.57 ; U3.26@3462.93,6804.89 cw(c3458.39,6800.36) 3464.8,6800.36 cw(c3471.21,6800.36) U3.26@3466.68,6804.89
NetR58_1: R58.1 U2.5 | length 280
  Bottom Layer w6.5: R58.1@5205,5716 5270.1,5781.1 U2.5@5363.23,5781.1 ; R58.1@5205,5727.25 ccw(c5205,5754.41) 5224.2,5735.2 ; R58.1@5205,5733.75 ccw(c5205,5776.6) 5235.3,5746.3 ; R58.1@5219.75,5719 cw(c5248.12,5719) 5228.06,5739.06 ; U2.5@5359.96,5777.83 ccw(c5352.06,5769.94) 5352.06,5781.1 ccw(c5352.06,5792.27) U2.5@5359.96,5784.37
NetR94_2: R94.2 U6.34 | length 150.4
  Top Layer w6.5: U6.34@5442.63,6639.3 5485.3,6639.3 5486,6640 v1(5486,6642)
  Bottom Layer w6.5: v1@5495.05,6639 ccw(c5495.05,6660.95) R94.2@5510.57,6645.43 ; 5497.68,6639 cw(c5497.68,6618.92) R94.2@5514.21,6630.32 ; R94.2@5508.86,6626.63 ccw(c5485.3,6610.39) 5485.3,6639 5520,6639 R94.2@5524,6635
NetR96_1: R96.1 U6.49 | length 143.2
  Top Layer w6.5: U6.49@5419.01,6938.62 5419.01,6954.01 v1(5443,6978) ; U6.49@5420.76,6947.4 cw(c5440.96,6947.4) 5426.68,6961.68
  Bottom Layer w6.5: v1(5443,6978) 5455,6990 ; R96.1@5447.43,7003.34 cw(c5439.46,6990) 5455,6990 ; R96.1@5455,7019 5455,6990 ; R96.1@5462.57,7003.34 ccw(c5470.54,6990) 5455,6990
NetR99_1: R99.1 U9.5 | length 124.9
  Bottom Layer w10: R99.1@5371.81,6473 cw(c5348.7,6449.9) 5381.38,6449.9 ; R99.1@5381,6482.2 5381.38,6481.82 U9.5@5381.38,6406.72 ; 5381.38,6451.72 cw(c5411.47,6451.72) R99.1@5390.19,6473
NetU9_2: U9.2 U9.3 | length 133.6
  Bottom Layer w6.5: 5128.87,6385.78 cw(c5137.79,6376.85) U9.3@5141.82,6388.82 ; U9.2@5178.62,6367.35 5129.65,6367.35 5127,6370 5127,6383.91 5130.13,6387.04 U9.3@5178.62,6387.04
PHY_RX_N: ETHERNET.6 J1.16 | length 1473
  Top Layer w8: ETHERNET.6@2818.38,6552.58 ccw(c2778.27,6512.47) 2778.27,6569.2 ccw(c2778.27,6625.93) ETHERNET.6@2818.38,6585.82 ; ETHERNET.6@2824.04,6558.24 ccw(c2797.58,6531.78) 2797.58,6569.2 ccw(c2797.58,6606.62) ETHERNET.6@2824.04,6580.16 ; ETHERNET.6@2835,6569.2 2729.8,6569.2 2679,6620 2665,6620 2640,6595 2640,6534 2959,6215 3389,6215 3416.25,6187.75 3416.25,6173.75 3434,6156 ; J1.16@3428.49,6146.17 ccw(c3422.49,6156) 3434,6156 ; J1.16@3435,6101 3434.73,6101.27 3434,6102 3434,6156 ; J1.16@3439.51,6146.17 cw(c3445.51,6156) 3434,6156
PHY_RX_P: ETHERNET.3 J1.14 | length 1417.5
  Top Layer w8: ETHERNET.3@2711.5,6719.2 cw(c2654.77,6719.2) 2694.88,6679.08 cw(c2735,6638.97) ETHERNET.3@2735,6695.7 ; ETHERNET.3@2719.5,6719.2 cw(c2682.08,6719.2) 2708.54,6692.74 cw(c2735,6666.28) ETHERNET.3@2735,6703.7 ; ETHERNET.3@2735,6719.2 2624,6608.2 2624,6529.49 2952.99,6200.5 3382.99,6200.5 3401.75,6181.74 3401.75,6173.75 3384,6156 ; J1.14@3378.49,6146.17 ccw(c3372.49,6156) 3384,6156 ; J1.14@3384,6100.54 3384,6156 ; J1.14@3389.51,6146.17 cw(c3395.51,6156) 3384,6156
PHY_TX_N: ETHERNET.2 J1.22 | length 2121
  Top Layer w8: 2754.85,6759.5 ccw(c2754.85,6849.35) ETHERNET.2@2818.38,6785.82 ; 2774.16,6759.5 ccw(c2774.16,6830.04) ETHERNET.2@2824.04,6780.16 ; 2793.48,6759.5 ccw(c2793.48,6810.72) ETHERNET.2@2829.7,6774.5 ; 2801.68,6759.5 cw(c2801.68,6735.88) ETHERNET.2@2818.38,6752.58 ; ETHERNET.2@2835,6769.2 2825.3,6759.5 2641.5,6759.5 2618,6783 2618,6845.51 2649.99,6877.5 2882.01,6877.5 2949,6810.51 2949,6399 3066,6282 3534.51,6282 3566.25,6250.26 3566.25,6173.75 3584,6156 ; J1.22@3578.49,6146.17 ccw(c3572.49,6156) 3584,6156 ; J1.22@3584,6100.54 3584,6156 ; J1.22@3589.51,6146.17 cw(c3595.51,6156) 3584,6156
